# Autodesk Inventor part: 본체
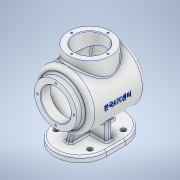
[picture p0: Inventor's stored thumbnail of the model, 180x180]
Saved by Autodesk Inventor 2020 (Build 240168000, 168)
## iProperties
Created: 2023-01
Part Number: 본체
Material: Aluminum 6061
Document SubType Name: Modeling
Designer: home
Density: 2.7 g/cm^3
Appearance: Aluminum - Flat
Mass: 1041.44 g
Surface Area: 1149.73 cm^2
Volume: 385.718 cm^3
Author: home
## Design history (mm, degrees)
sketch "Sketch1"
  geometry: L1 (0, 61)-(0, -61); L2 (38, 61)-(38, 49); L3 (38, 49)-(50, 49); L4 (38, 61)-(27, 61); L5 (27, 61)-(27, 44); L6 (27, 44)-(45, 44); L7 (45, 44)-(45, -45.821); L8 (50, 49)-(50, -49); A1 r 120 centre (-2.354, 58.977) between (0, -61) and (50, -49); A2 r 115 centre (-2.354, 58.977) between (0, -55.999) and (45, -45.821); 3 further points
  constraints: 16 end point, 4 point on circle, 4 vertical, 3 perpendicular, 2 centre point, 2 coincident, 2 midpoint, 1 horizontal, 1 horizontal alignment, 1 point on line
  dimensions: "d0" = 122 distance of L1.start L1.end; "d2" = 120 radius of A1; "d3" = 5 radial gap between concentric circles of A1 A2; "d5" = 122 distance from line of L1.end L4; "d7" = 100 diameter of L8 L1; "d8" = 90 diameter of L7 L1; "d9" = 54 diameter of L5 L1; "d10" = 76 diameter of L2 L1; "d11" = 17 distance of L4.end L5.end; "d90" = 110 distance from line of L1.end L3
revolve "Revolution1" sketch "Sketch1" stored, may be unused: angle "d13" = 90 deg
workplane "Work Plane1"
sketch "Sketch2"
  geometry: L1 (0, 63)-(0, -63); L2 (-46.038, 16.963)-(-46.038, -16.962); L3 (46.038, -16.963)-(46.038, 16.962); A1 r 46.038 centre (0, 16.963) between (46.038, 16.962) and (-46.038, 16.963); A2 r 46.038 centre (0, -16.962) between (-46.038, -16.962) and (46.038, -16.963); 2 further points
  constraints: 8 end point, 6 point on circle, 4 tangent, 2 centre point, 2 point on line, 1 coincident, 1 midpoint, 1 parallel, 1 vertical
  dimensions: "d15" = 126 distance of L1.start L1.end; "d16" = 46.0375 radius of A2
extrude "Extrusion1" join sketch "Sketch2" distance "d17" = 10; taper "d18" = 0 deg
workplane "Work Plane3"
  workplane "Work Plane2"
sketch "Sketch3"
  geometry: C1 r 38 at (0, 0); 1 further point
  constraints: 1 centre point, 1 coincident
  dimensions: "d20" = 76 diameter of C1
extrude "Extrusion2" join sketch "Sketch3" stored distance "d21" = 10; taper "d22" = 0 deg
sketch "Sketch4"
  geometry: C1 r 27 at (0, 0); 1 further point
  constraints: 1 centre point, 1 coincident
  dimensions: "d23" = 54 diameter of C1
extrude "Extrusion3" cut sketch "Sketch4" stored distance "d24" = 0; taper "d25" = 0 deg
sketch "Sketch5" dims "d26" = 65
  geometry: 3 further points
  constraints: 1 coincident, 1 horizontal alignment, 2 other
hole "Hole1" sketch "Sketch5" at (-32.5, 0) diameter "d27" = 3.242; stored, may be unused: countersink angle "d31" = 90 deg, drill point angle "d33" = 118 deg; dims "d28" = 8, "d29" = 4, "d30" = 2, "d32" = 10
pattern_circular "Circular Pattern1" dims angle "d35" = 360 deg
sketch "Sketch6" dims "d37" = 65
  geometry: 3 further points
  constraints: 1 coincident, 1 vertical alignment, 2 other
hole "Hole2" sketch "Sketch6" at (0, 32.5) diameter "d38" = 3.242; stored, may be unused: countersink angle "d42" = 90 deg, drill point angle "d44" = 118 deg; dims "d39" = 8, "d40" = 4, "d41" = 2, "d43" = 10
pattern_circular "Circular Pattern2" dims angle "d46" = 360 deg
fillet "Fillet1" dims "d48" = 3
chamfer "Chamfer1" distance "d49" = 1; stored, may be unused: second distance "d50" = 2, angle "d51" = 45 deg
sketch "Sketch7"
  geometry: L1 (46.038, -70)-(-46.038, -70) reference; L2 (-35, -70)-(-35, -35.707); L3 (35, -70)-(35, -35.707); A1 r 50 centre (0, 0) between (-35, -35.707) and (35, -35.707) reference; A2 r 50 centre (0, 0) between (-35, -35.707) and (35, -35.707); 1 further point
  constraints: 4 end point, 4 point on circle, 2 point on line, 2 vertical, 1 centre point, 1 coincident
  dimensions: "d52" = 70 distance between parallel lines of L3 L2; "d53" = 35 distance from line of L3 point (0, 0)
feature "Rib1" sketch "Sketch7" dims "d54" = 1, "d55" = 10, "d56" = 0, "d57" = 0, "d58" = 1, "d59" = 1
sketch "Sketch8"
  geometry: L1 (-70, 16.962)-(-70, 63) reference; L2 (-70, 40)-(-46.143, 33.608); L3 (-46.143, 33.608)-(-46.143, -33.608); L4 (-50, 49)-(-50, -49) reference; L5 (-46.143, -33.608)-(-70, -40); L6 (-70, -63)-(-70, -16.962) reference; 1 further point
  constraints: 6 end point, 2 point on line, 1 parallel
  dimensions: "d60" = 23 distance of L2.start L1.end; "d61" = 80 distance of L5.end L2.start; "d62" = 105 deg angle of L1 L2; "d63" = 105 deg angle of L6 L5
feature "Rib2" sketch "Sketch8" dims "d64" = 1, "d65" = 10, "d66" = 0, "d67" = 0, "d68" = 1, "d69" = 1
fillet "Fillet2" dims "d70" = 8
fillet "Fillet3" dims "d71" = 3
sketch "Sketch9"
  geometry: 5 further points
  constraints: 1 horizontal alignment, 1 vertical alignment
  dimensions: "d72" = 60 distance of point (30, -30) point (-30, -30); "d73" = 30 horizontal distance of point (0, 0) point (-30, -30); "d74" = 60 vertical distance of point (-30.769, 30) point (-30, -30); "d75" = 30 horizontal distance of point (0, 0) point (-30, -30)
hole "Hole3" sketch "Sketch9" at (-30, -30), (-30.769, 30), (30, -30), (30, 30) diameter "d76" = 9; stored, may be unused: countersink angle "d80" = 90 deg, drill point angle "d82" = 0 deg; dims "d77" = 8, "d78" = 4, "d79" = 2, "d81" = 10
fillet "Fillet4" dims "d83" = 3
fillet "Fillet5" dims "d84" = 3
fillet "Fillet6" dims "d85" = 3
chamfer "Chamfer2" distance "d86" = 1; stored, may be unused: second distance "d87" = 2, angle "d88" = 45 deg
workplane "Work Plane5"
sketch "Sketch11"
  geometry: L1 (4.5, 25)-(4.5, -25); L2 (4.5, -25)-(-4.5, -25); L3 (-4.5, -25)-(-4.5, 25); L4 (-4.5, 25)-(4.5, 25); L5 (-80, -63)-(-80, -16.962) reference; 1 further point
  constraints: 2 other
  dimensions: "d91" = 50 distance between parallel lines of L4 L2; "d92" = 9 distance between parallel lines of L3 L1; "d93" = 25 distance from line of point (0, 0) L2; "d94" = 84.5 distance between parallel lines of L5 L1
emboss "Emboss1" sketch "Sketch11" dims "d15" = 126, "d16" = 46.0375, "d95" = 0.5, "d96" = 0
body "Solid1"
other parameters: "d19" = 14
